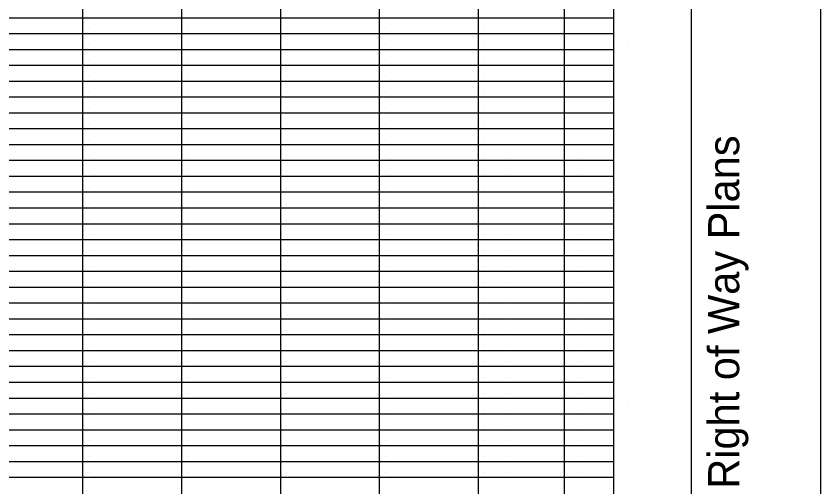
# Model space of a CAD drawing. Extents: x 0 to 3.48, y 0 to 2.25.
# Drawn here: x 1.913 to 2.95, y 0.479 to 1.085 of the extents above; entities that cross this region are included whole.
import ezdxf

# ---------------------------------------------------------------- set-up
doc = ezdxf.new("R2010")
doc.units = 0
for name, color, linetype in [('Border Active Points', 7, 'Continuous'), ('Border Line', 7, 'Continuous'), ('Level 2', 7, 'Continuous')]:
    doc.layers.add(name, color=color, linetype=linetype)

msp = doc.modelspace()

# ---------------------------------------------------------------- linework, layer by layer
at = {"layer": 'Border Active Points'}
for p, q in [((2.007, 1.0681), (2.007, 1.0681)), ((2.1345, 1.0681), (2.1345, 1.0681)), ((2.262, 1.0681), (2.262, 1.0681)), ((2.3895, 1.0681), (2.3895, 1.0681)), ((2.517, 1.0681), (2.517, 1.0681)), ((2.5453, 1.0681), (2.5453, 1.0681)), ((2.641, 1.0681), (2.641, 1.0681)), ((2.007, 1.0477), (2.007, 1.0477)), ((2.1345, 1.0477), (2.1345, 1.0477)), ((2.262, 1.0477), (2.262, 1.0477)), ((2.3895, 1.0477), (2.3895, 1.0477)), ((2.517, 1.0477), (2.517, 1.0477)), ((2.5453, 1.0477), (2.5453, 1.0477)), ((2.641, 1.0477), (2.641, 1.0477)), ((2.7002, 1.0514), (2.7002, 1.0514)), ((2.007, 1.0273), (2.007, 1.0273)), ((2.1345, 1.0273), (2.1345, 1.0273)), ((2.262, 1.0273), (2.262, 1.0273)), ((2.3895, 1.0273), (2.3895, 1.0273)), ((2.517, 1.0273), (2.517, 1.0273)), ((2.5453, 1.0273), (2.5453, 1.0273)), ((2.641, 1.0273), (2.641, 1.0273)), ((2.007, 1.0069), (2.007, 1.0069)), ((2.1345, 1.0069), (2.1345, 1.0069)), ((2.262, 1.0069), (2.262, 1.0069)), ((2.3895, 1.0069), (2.3895, 1.0069)), ((2.517, 1.0069), (2.517, 1.0069)), ((2.5453, 1.0069), (2.5453, 1.0069)), ((2.641, 1.0069), (2.641, 1.0069)), ((2.5551, 1), (2.5551, 1)), ((2.007, 0.9865), (2.007, 0.9865)), ((2.1345, 0.9865), (2.1345, 0.9865)), ((2.262, 0.9865), (2.262, 0.9865)), ((2.3895, 0.9865), (2.3895, 0.9865)), ((2.517, 0.9865), (2.517, 0.9865)), ((2.5453, 0.9865), (2.5453, 0.9865)), ((2.641, 0.9865), (2.641, 0.9865)), ((2.007, 0.9661), (2.007, 0.9661)), ((2.1345, 0.9661), (2.1345, 0.9661)), ((2.262, 0.9661), (2.262, 0.9661)), ((2.3895, 0.9661), (2.3895, 0.9661)), ((2.517, 0.9661), (2.517, 0.9661)), ((2.5453, 0.9661), (2.5453, 0.9661)), ((2.641, 0.9661), (2.641, 0.9661)), ((2.007, 0.9457), (2.007, 0.9457)), ((2.1345, 0.9457), (2.1345, 0.9457)), ((2.262, 0.9457), (2.262, 0.9457)), ((2.3895, 0.9457), (2.3895, 0.9457)), ((2.517, 0.9457), (2.517, 0.9457)), ((2.5453, 0.9457), (2.5453, 0.9457)), ((2.641, 0.9457), (2.641, 0.9457)), ((2.007, 0.9253), (2.007, 0.9253)), ((2.1345, 0.9253), (2.1345, 0.9253)), ((2.262, 0.9253), (2.262, 0.9253)), ((2.3895, 0.9253), (2.3895, 0.9253)), ((2.517, 0.9253), (2.517, 0.9253)), ((2.5453, 0.9253), (2.5453, 0.9253)), ((2.641, 0.9253), (2.641, 0.9253)), ((2.007, 0.9049), (2.007, 0.9049)), ((2.1345, 0.9049), (2.1345, 0.9049)), ((2.262, 0.9049), (2.262, 0.9049)), ((2.3895, 0.9049), (2.3895, 0.9049)), ((2.517, 0.9049), (2.517, 0.9049)), ((2.5453, 0.9049), (2.5453, 0.9049)), ((2.641, 0.9049), (2.641, 0.9049)), ((2.007, 0.8845), (2.007, 0.8845)), ((2.1345, 0.8845), (2.1345, 0.8845)), ((2.262, 0.8845), (2.262, 0.8845)), ((2.3895, 0.8845), (2.3895, 0.8845)), ((2.517, 0.8845), (2.517, 0.8845)), ((2.5453, 0.8845), (2.5453, 0.8845)), ((2.641, 0.8845), (2.641, 0.8845)), ((2.007, 0.8641), (2.007, 0.8641)), ((2.1345, 0.8641), (2.1345, 0.8641)), ((2.262, 0.8641), (2.262, 0.8641)), ((2.3895, 0.8641), (2.3895, 0.8641)), ((2.517, 0.8641), (2.517, 0.8641)), ((2.5453, 0.8641), (2.5453, 0.8641)), ((2.641, 0.8641), (2.641, 0.8641)), ((2.007, 0.8437), (2.007, 0.8437)), ((2.1345, 0.8437), (2.1345, 0.8437)), ((2.262, 0.8437), (2.262, 0.8437)), ((2.3895, 0.8437), (2.3895, 0.8437)), ((2.517, 0.8437), (2.517, 0.8437)), ((2.5453, 0.8437), (2.5453, 0.8437)), ((2.641, 0.8437), (2.641, 0.8437)), ((2.007, 0.8233), (2.007, 0.8233)), ((2.1345, 0.8233), (2.1345, 0.8233)), ((2.262, 0.8233), (2.262, 0.8233)), ((2.3895, 0.8233), (2.3895, 0.8233)), ((2.517, 0.8233), (2.517, 0.8233)), ((2.5453, 0.8233), (2.5453, 0.8233)), ((2.641, 0.8233), (2.641, 0.8233)), ((2.007, 0.8029), (2.007, 0.8029)), ((2.1345, 0.8029), (2.1345, 0.8029)), ((2.262, 0.8029), (2.262, 0.8029)), ((2.3895, 0.8029), (2.3895, 0.8029)), ((2.517, 0.8029), (2.517, 0.8029)), ((2.5453, 0.8029), (2.5453, 0.8029)), ((2.641, 0.8029), (2.641, 0.8029)), ((2.007, 0.7825), (2.007, 0.7825)), ((2.1345, 0.7825), (2.1345, 0.7825)), ((2.262, 0.7825), (2.262, 0.7825)), ((2.3895, 0.7825), (2.3895, 0.7825)), ((2.517, 0.7825), (2.517, 0.7825)), ((2.5453, 0.7825), (2.5453, 0.7825)), ((2.641, 0.7825), (2.641, 0.7825)), ((2.007, 0.7621), (2.007, 0.7621)), ((2.1345, 0.7621), (2.1345, 0.7621)), ((2.262, 0.7621), (2.262, 0.7621)), ((2.3895, 0.7621), (2.3895, 0.7621)), ((2.517, 0.7621), (2.517, 0.7621)), ((2.5453, 0.7621), (2.5453, 0.7621)), ((2.641, 0.7621), (2.641, 0.7621)), ((2.007, 0.7417), (2.007, 0.7417)), ((2.1345, 0.7417), (2.1345, 0.7417)), ((2.262, 0.7417), (2.262, 0.7417)), ((2.3895, 0.7417), (2.3895, 0.7417)), ((2.517, 0.7417), (2.517, 0.7417)), ((2.5453, 0.7417), (2.5453, 0.7417)), ((2.641, 0.7417), (2.641, 0.7417)), ((2.007, 0.7213), (2.007, 0.7213)), ((2.1345, 0.7213), (2.1345, 0.7213)), ((2.262, 0.7213), (2.262, 0.7213)), ((2.3895, 0.7213), (2.3895, 0.7213)), ((2.517, 0.7213), (2.517, 0.7213)), ((2.5453, 0.7213), (2.5453, 0.7213)), ((2.641, 0.7213), (2.641, 0.7213)), ((2.007, 0.7009), (2.007, 0.7009)), ((2.1345, 0.7009), (2.1345, 0.7009)), ((2.262, 0.7009), (2.262, 0.7009)), ((2.3895, 0.7009), (2.3895, 0.7009)), ((2.517, 0.7009), (2.517, 0.7009)), ((2.5453, 0.7009), (2.5453, 0.7009)), ((2.641, 0.7009), (2.641, 0.7009)), ((2.007, 0.6805), (2.007, 0.6805)), ((2.1345, 0.6805), (2.1345, 0.6805)), ((2.262, 0.6805), (2.262, 0.6805)), ((2.3895, 0.6805), (2.3895, 0.6805)), ((2.517, 0.6805), (2.517, 0.6805)), ((2.5453, 0.6805), (2.5453, 0.6805)), ((2.641, 0.6805), (2.641, 0.6805)), ((2.007, 0.6601), (2.007, 0.6601)), ((2.1345, 0.6601), (2.1345, 0.6601)), ((2.262, 0.6601), (2.262, 0.6601)), ((2.3895, 0.6601), (2.3895, 0.6601)), ((2.517, 0.6601), (2.517, 0.6601)), ((2.5453, 0.6601), (2.5453, 0.6601)), ((2.641, 0.6601), (2.641, 0.6601)), ((2.007, 0.6397), (2.007, 0.6397)), ((2.1345, 0.6397), (2.1345, 0.6397)), ((2.262, 0.6397), (2.262, 0.6397)), ((2.3895, 0.6397), (2.3895, 0.6397)), ((2.517, 0.6397), (2.517, 0.6397)), ((2.5453, 0.6397), (2.5453, 0.6397)), ((2.641, 0.6397), (2.641, 0.6397)), ((2.007, 0.6193), (2.007, 0.6193)), ((2.1345, 0.6193), (2.1345, 0.6193)), ((2.262, 0.6193), (2.262, 0.6193)), ((2.3895, 0.6193), (2.3895, 0.6193)), ((2.517, 0.6193), (2.517, 0.6193)), ((2.5453, 0.6193), (2.5453, 0.6193)), ((2.641, 0.6193), (2.641, 0.6193)), ((2.007, 0.5989), (2.007, 0.5989)), ((2.1345, 0.5989), (2.1345, 0.5989)), ((2.262, 0.5989), (2.262, 0.5989)), ((2.3895, 0.5989), (2.3895, 0.5989)), ((2.517, 0.5989), (2.517, 0.5989)), ((2.5453, 0.5989), (2.5453, 0.5989)), ((2.641, 0.5989), (2.641, 0.5989)), ((2.7002, 0.5849), (2.7002, 0.5849)), ((2.007, 0.5786), (2.007, 0.5786)), ((2.1345, 0.5786), (2.1345, 0.5786)), ((2.262, 0.5786), (2.262, 0.5786)), ((2.3895, 0.5786), (2.3895, 0.5786)), ((2.517, 0.5786), (2.517, 0.5786)), ((2.5453, 0.5786), (2.5453, 0.5786)), ((2.641, 0.5786), (2.641, 0.5786)), ((2.007, 0.5582), (2.007, 0.5582)), ((2.1345, 0.5582), (2.1345, 0.5582)), ((2.262, 0.5582), (2.262, 0.5582)), ((2.3895, 0.5582), (2.3895, 0.5582)), ((2.517, 0.5582), (2.517, 0.5582)), ((2.5453, 0.5582), (2.5453, 0.5582)), ((2.641, 0.5582), (2.641, 0.5582)), ((2.007, 0.5378), (2.007, 0.5378)), ((2.1345, 0.5378), (2.1345, 0.5378)), ((2.262, 0.5378), (2.262, 0.5378)), ((2.3895, 0.5378), (2.3895, 0.5378)), ((2.517, 0.5378), (2.517, 0.5378)), ((2.5453, 0.5378), (2.5453, 0.5378)), ((2.5551, 0.5335), (2.5551, 0.5335)), ((2.641, 0.5378), (2.641, 0.5378)), ((2.007, 0.5174), (2.007, 0.5174)), ((2.1345, 0.5174), (2.1345, 0.5174)), ((2.262, 0.5174), (2.262, 0.5174)), ((2.3895, 0.5174), (2.3895, 0.5174)), ((2.517, 0.5174), (2.517, 0.5174)), ((2.5453, 0.5174), (2.5453, 0.5174)), ((2.641, 0.5174), (2.641, 0.5174)), ((2.007, 0.497), (2.007, 0.497)), ((2.1345, 0.497), (2.1345, 0.497)), ((2.262, 0.497), (2.262, 0.497)), ((2.3895, 0.497), (2.3895, 0.497)), ((2.517, 0.497), (2.517, 0.497)), ((2.5453, 0.497), (2.5453, 0.497)), ((2.641, 0.497), (2.641, 0.497))]:
    msp.add_line(p, q, dxfattribs=at)
at = {"layer": 'Border Line'}
for p, q in [((2.7834, 0.0835), (2.7834, 1.9165)), ((2.6827, 1.681), (2.6827, 0.185)), ((1.9985, 1.6555), (1.9985, 0.185)), ((2.2535, 1.6555), (2.2535, 0.185)), ((2.5085, 1.6555), (2.5085, 0.185)), ((2.619, 1.6555), (2.619, 0.185)), ((2.126, 1.6342), (2.126, 0.185)), ((2.381, 1.6342), (2.381, 0.185)), ((0.2177, 1.0826), (2.6827, 1.0826)), ((0.2177, 1.0622), (2.6827, 1.0622)), ((0.2177, 1.0418), (2.6827, 1.0418)), ((0.2177, 1.0214), (2.6827, 1.0214)), ((0.2177, 1.001), (2.6827, 1.001)), ((0.2177, 0.9806), (2.6827, 0.9806)), ((0.2177, 0.9602), (2.6827, 0.9602)), ((0.2177, 0.9398), (2.6827, 0.9398)), ((0.2177, 0.9194), (2.6827, 0.9194)), ((0.2177, 0.899), (2.6827, 0.899)), ((0.2177, 0.8786), (2.6827, 0.8786)), ((0.2177, 0.8582), (2.6827, 0.8582)), ((0.2177, 0.8378), (2.6827, 0.8378)), ((0.2177, 0.8174), (2.6827, 0.8174)), ((0.2177, 0.797), (2.6827, 0.797)), ((0.2177, 0.7766), (2.6827, 0.7766)), ((0.2177, 0.7562), (2.6827, 0.7562)), ((0.2177, 0.7358), (2.6827, 0.7358)), ((0.2177, 0.7154), (2.6827, 0.7154)), ((0.2177, 0.695), (2.6827, 0.695)), ((0.2177, 0.6746), (2.6827, 0.6746)), ((0.2177, 0.6542), (2.6827, 0.6542)), ((0.2177, 0.6338), (2.6827, 0.6338)), ((0.2177, 0.6134), (2.6827, 0.6134)), ((0.2177, 0.593), (2.6827, 0.593)), ((0.2177, 0.5726), (2.6827, 0.5726)), ((0.2177, 0.5522), (2.6827, 0.5522)), ((0.2177, 0.5318), (2.6827, 0.5318)), ((0.2177, 0.5114), (2.6827, 0.5114)), ((0.2177, 0.491), (2.6827, 0.491))]:
    msp.add_line(p, q, dxfattribs=at)
msp.add_lwpolyline([(0.117, 0.0835), (2.95, 0.0835), (2.95, 1.9165), (0.117, 1.9165)], close=True, dxfattribs=at)

# ---------------------------------------------------------------- texts
at = {"layer": 'Level 2'}
msp.add_text('Right of Way Plans', height=0.04, rotation=90, dxfattribs=at).set_placement((2.8447, 0.4762))

doc.saveas('drawing.dxf')
